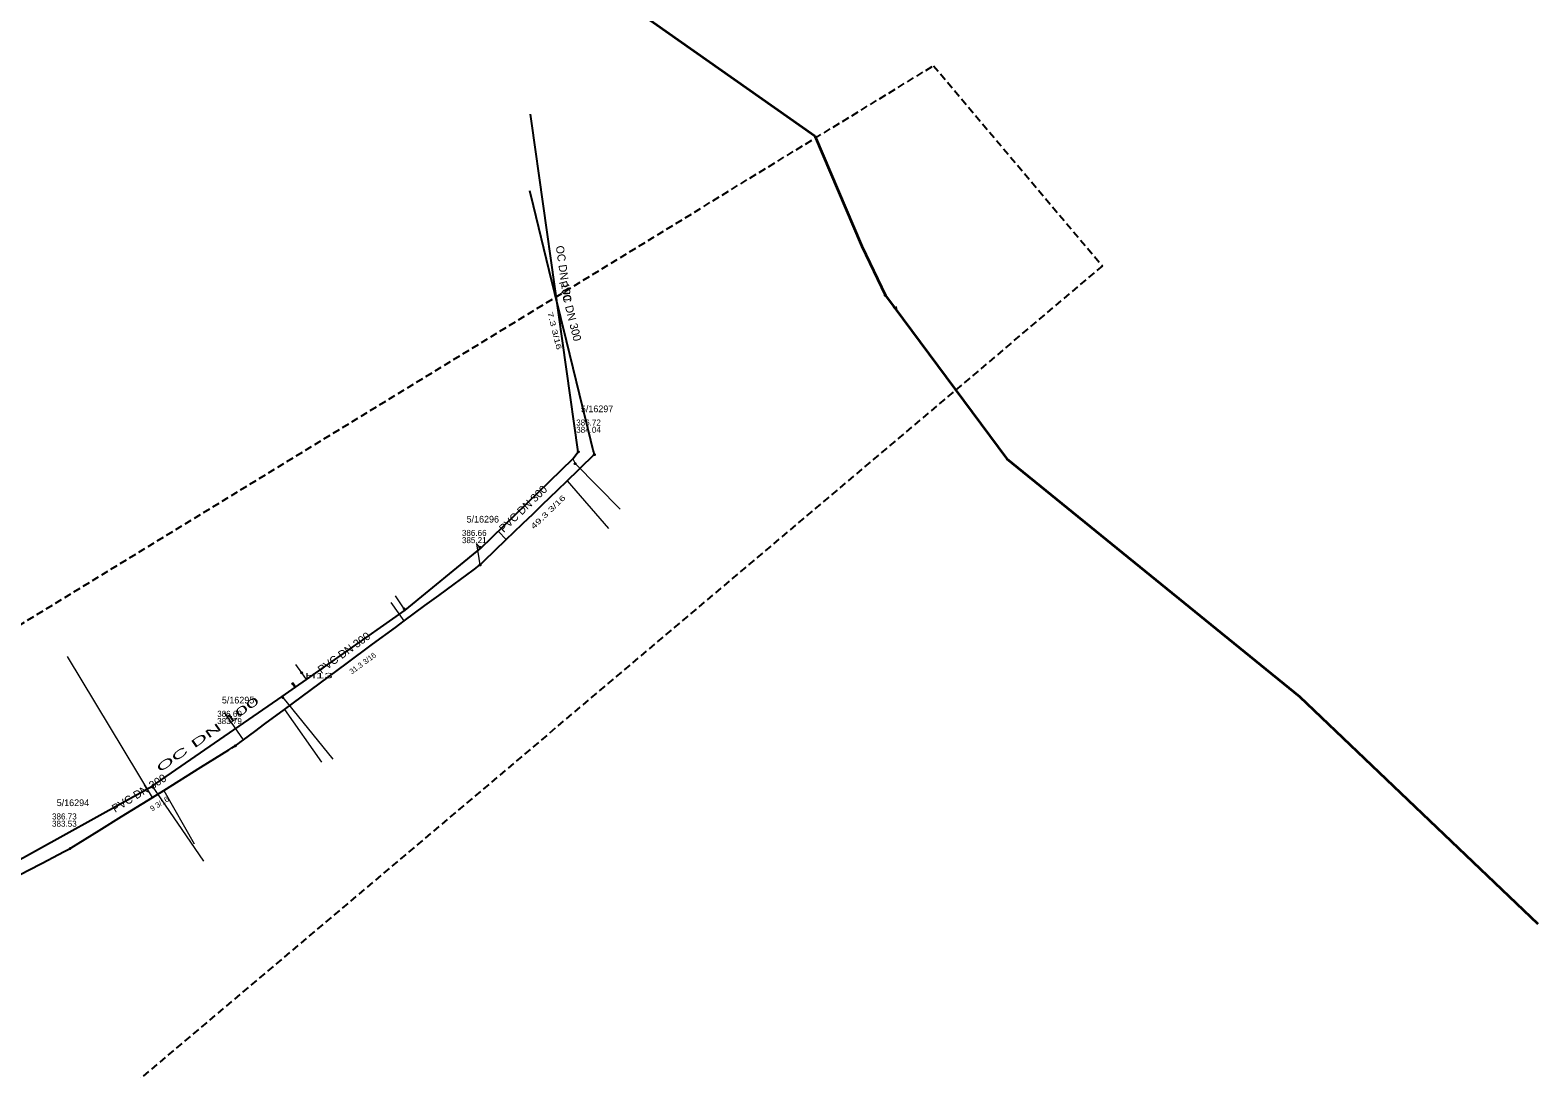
# Model space of a CAD drawing. Extents: x -772855 to -772151, y -1033136 to -1032581.
# Drawn here: x -772376 to -772151.1, y -1032956.5 to -1032801.5 of the extents above; entities that cross this region are included whole.
import ezdxf

# ---------------------------------------------------------------- set-up
doc = ezdxf.new("R2010")
doc.units = 0
doc.header["$LTSCALE"] = 0.36
doc.header["$PDMODE"] = 32
doc.header["$PDSIZE"] = 0.18
doc.linetypes.add('DOT_DASHED', pattern=[7.7, 5, -1.2, 0.3, -1.2])
doc.linetypes.add('MEDIUM_DASHED', pattern=[4.5, 3, -1.5])
for name, color, linetype in [('15', 7, 'Continuous'), ('17', 7, 'Continuous'), ('20', 7, 'Continuous'), ('21', 7, 'Continuous'), ('3', 7, 'Continuous'), ('4', 7, 'Continuous'), ('5', 7, 'Continuous'), ('56', 7, 'Continuous')]:
    doc.layers.add(name, color=color, linetype=linetype)
for name, color, linetype, lineweight in [('16', 7, 'Continuous', 25), ('2', 7, 'Continuous', 25), ('41', 7, 'DOT_DASHED', 35), ('57', 7, 'Continuous', 13), ('58', 7, 'Continuous', 13), ('62', 7, 'MEDIUM_DASHED', 25)]:
    doc.layers.add(name, color=color, linetype=linetype, lineweight=lineweight)

msp = doc.modelspace()

# ---------------------------------------------------------------- linework, layer by layer
at = {"layer": '15'}
for p in [(-772248.45, -1032841.09), (-772294.264, -1032864.446), (-772294.737, -1032866.211), (-772308.938, -1032878.708), (-772320.242, -1032887.886), (-772335.526, -1032897.422), (-772336.666, -1032899.313), (-772338.356, -1032901.119), (-772357.823, -1032914.385)]:
    msp.add_point(p, dxfattribs=at)
at = {"layer": '16', "lineweight": 35}
for points in [[(-772573.62, -1032580.91), (-772544.449, -1032601.839), (-772487.239, -1032639.739), (-772409.829, -1032692.94), (-772349.25, -1032742.28), (-772336.339, -1032755.28), (-772324.109, -1032770.089), (-772310.5, -1032781.71), (-772304.089, -1032786.42), (-772295.059, -1032791.859), (-772258.989, -1032817.269), (-772251.94, -1032833.739), (-772248.449, -1032841.089)], [(-772248.449, -1032841.089), (-772230.335, -1032865.497), (-772186.679, -1032900.96), (-772151.109, -1032934.89)]]:
    msp.add_lwpolyline(points, dxfattribs=at)
at = {"layer": '16'}
for points in [[(-772294.263, -1032864.445), (-772301.245, -1032815.115), (-772301.398, -1032814.033)], [(-772415.739, -1032946.164), (-772401.855, -1032938.587), (-772379.355, -1032926.307), (-772357.856, -1032914.338), (-772338.431, -1032900.962), (-772336.468, -1032899.579), (-772334.822, -1032898.421), (-772320.116, -1032888.065), (-772308.796, -1032878.817), (-772295.074, -1032865.513), (-772294.263, -1032864.445)]]:
    msp.add_lwpolyline(points, dxfattribs=at)
at = {"layer": '2'}
for points in [[(-772291.88, -1032864.86), (-772291.919, -1032864.697), (-772291.968, -1032864.499), (-772292.033, -1032864.215), (-772292.094, -1032863.982), (-772292.693, -1032861.525), (-772293.08, -1032859.943), (-772296.027, -1032847.87), (-772298.591, -1032837.362), (-772300.943, -1032827.729), (-772301.491, -1032825.485)], [(-772308.93, -1032881.33), (-772308.334, -1032880.754), (-772305.002, -1032877.526), (-772303.867, -1032876.439), (-772302.531, -1032875.149), (-772301.011, -1032873.68), (-772299.649, -1032872.364), (-772298.462, -1032871.218), (-772297.349, -1032870.143), (-772295.918, -1032868.76), (-772294.255, -1032867.154), (-772293.424, -1032866.352), (-772292.446, -1032865.406), (-772292.144, -1032865.115), (-772291.88, -1032864.86)], [(-772345.44, -1032908.33), (-772345.022, -1032908.021), (-772344.761, -1032907.828), (-772344.192, -1032907.408), (-772342.511, -1032906.164), (-772341.024, -1032905.064), (-772338.084, -1032902.89), (-772328.873, -1032896.078), (-772324.947, -1032893.174), (-772321.521, -1032890.641), (-772320.226, -1032889.683), (-772317.141, -1032887.402), (-772315.067, -1032885.868), (-772312.803, -1032884.194), (-772309.962, -1032882.093), (-772309.553, -1032881.791), (-772309.188, -1032881.521), (-772308.93, -1032881.33)], [(-772370.08, -1032923.65), (-772369.521, -1032923.302), (-772368.87, -1032922.897), (-772365.746, -1032920.955), (-772362.396, -1032918.872), (-772357.815, -1032916.024), (-772356.123, -1032914.972), (-772350.573, -1032911.521), (-772346.379, -1032908.913), (-772345.944, -1032908.643), (-772345.44, -1032908.33)], [(-772413.9, -1032946.45), (-772413.42, -1032946.2), (-772412.857, -1032945.907), (-772407.577, -1032943.16), (-772403.768, -1032941.178), (-772399.916, -1032939.173), (-772395.222, -1032936.731), (-772390.907, -1032934.486), (-772385.235, -1032931.535), (-772382.615, -1032930.172), (-772376.302, -1032926.887), (-772374.27, -1032925.83), (-772371.818, -1032924.554), (-772370.95, -1032924.102), (-772370.586, -1032923.913), (-772370.08, -1032923.65)]]:
    msp.add_lwpolyline(points, dxfattribs=at)
at = {"layer": '20'}
msp.add_point((-772336.863, -1032899.044), dxfattribs=at)
at = {"layer": '21'}
msp.add_point((-772248.449, -1032841.089), dxfattribs=at)
at = {"layer": '4'}
for p in [(-772291.88, -1032864.86), (-772308.93, -1032881.33), (-772345.44, -1032908.329), (-772370.08, -1032923.65)]:
    msp.add_point(p, dxfattribs=at)
at = {"layer": '41', "linetype": 'Continuous', "lineweight": 13}
for q in [(-772247.209, -1032842.807), (-772247.209, -1032842.807), (-772247.209, -1032842.807), (-772247.209, -1032842.807), (-772246.749, -1032843.195), (-772246.749, -1032843.195), (-772246.749, -1032843.195), (-772246.749, -1032843.195)]:
    msp.add_line((-772246.974, -1032842.99), q, dxfattribs=at)
at = {"layer": '41'}
for q in [(-772247.209, -1032842.807), (-772247.209, -1032842.807), (-772247.209, -1032842.807), (-772247.209, -1032842.807), (-772247.209, -1032842.807), (-772247.209, -1032842.807), (-772247.209, -1032842.807), (-772247.209, -1032842.807), (-772246.749, -1032843.195), (-772246.749, -1032843.195), (-772246.749, -1032843.195), (-772246.749, -1032843.195), (-772246.749, -1032843.195), (-772246.749, -1032843.195), (-772246.749, -1032843.195), (-772246.749, -1032843.195)]:
    msp.add_line((-772246.974, -1032842.99), q, dxfattribs=at)
at = {"layer": '41', "linetype": 'MEDIUM_DASHED', "lineweight": 25}
msp.add_line((-772246.974, -1032842.99), (-772246.731, -1032842.736), dxfattribs=at)
msp.add_line((-772246.974, -1032842.99), (-772246.731, -1032842.736), dxfattribs=at)
msp.add_line((-772246.974, -1032842.99), (-772246.731, -1032842.736), dxfattribs=at)
msp.add_line((-772246.974, -1032842.99), (-772246.731, -1032842.736), dxfattribs=at)
at = {"layer": '56'}
msp.add_point((-772246.974, -1032842.99), dxfattribs=at)
at = {"layer": '57'}
for p, q in [((-772295.918, -1032868.76), (-772289.77, -1032875.91)), ((-772305.002, -1032877.526), (-772306.15, -1032876.33)), ((-772308.93, -1032881.33), (-772309.381, -1032878.18)), ((-772320.226, -1032889.683), (-772322.18, -1032886.95)), ((-772357.815, -1032916.024), (-772370.48, -1032894.99)), ((-772338.084, -1032902.89), (-772332.59, -1032910.75)), ((-772356.123, -1032914.972), (-772351.59, -1032922.94))]:
    msp.add_line(p, q, dxfattribs=at)
msp.add_lwpolyline([(-772344.192, -1032907.408), (-772346.001, -1032904.823), (-772347.04, -1032903.34)], dxfattribs=at)
at = {"layer": '58'}
for p, q in [((-772338.431, -1032900.962), (-772338.356, -1032901.119)), ((-772338.355, -1032901.118), (-772330.887, -1032910.328)), ((-772357.856, -1032914.338), (-772350.181, -1032925.515))]:
    msp.add_line(p, q, dxfattribs=at)
for points in [[(-772295.074, -1032865.514), (-772294.738, -1032866.211), (-772287.994, -1032873.011)], [(-772308.796, -1032878.816), (-772308.938, -1032878.708), (-772309.463, -1032878.124)], [(-772320.117, -1032888.065), (-772320.242, -1032887.886), (-772321.513, -1032885.928)], [(-772334.823, -1032898.421), (-772335.526, -1032897.422), (-772336.395, -1032896.189)], [(-772336.468, -1032899.579), (-772336.666, -1032899.313), (-772336.863, -1032899.044)]]:
    msp.add_lwpolyline(points, dxfattribs=at)
at = {"layer": '62'}
msp.add_lwpolyline([(-772807.858, -1033073.22), (-772807.858, -1033073.204), (-772761.644, -1033042.737), (-772462.077, -1032942.017), (-772241.248, -1032806.814), (-772216.072, -1032836.7), (-772367.717, -1032964.854), (-772756.015, -1033111.568)], close=True, dxfattribs=at)

# ---------------------------------------------------------------- texts
at = {"layer": '17'}
msp.add_text('OC DN 100 ', height=1.2, rotation=278, dxfattribs=at).set_placement((-772297.625, -1032833.756))
at = {"layer": '17', "width": 2.2}
msp.add_text('OC DN 100 ', height=1.2, rotation=35, dxfattribs=at).set_placement((-772356.687, -1032912.339))
at = {"layer": '20', "width": 2.1}
msp.add_text('H13 ', height=0.8, dxfattribs=at).set_placement((-772335.037, -1032898.239))
at = {"layer": '3'}
for s, height, rotation, p in [('PVC DN 300', 1.2, 284, (-772297.164, -1032839.111)), ('PVC DN 300', 1.2, 44, (-772305.395, -1032876.564)), ('PVC DN 300', 1.2, 36, (-772332.587, -1032897.615)), ('31.3 3/16', 0.8, 36, (-772328.058, -1032897.683)), ('PVC DN 300', 1.2, 32, (-772363.368, -1032918.332)), ('9 3/16 ', 0.8, 32, (-772357.84, -1032918.131))]:
    msp.add_text(s, height=height, rotation=rotation, dxfattribs=at).set_placement(p)
at = {"layer": '3', "width": 1.5}
for s, rotation, p in [('7.3 3/16 ', 284, (-772298.884, -1032843.65)), ('49.3 3/16', 44, (-772300.895, -1032876.039))]:
    msp.add_text(s, height=0.8, rotation=rotation, dxfattribs=at).set_placement(p)
at = {"layer": '5'}
for s, p in [('5/16297', (-772293.88, -1032858.531)), ('5/16296', (-772310.93, -1032875.001)), ('5/16295', (-772347.44, -1032902.001)), ('5/16294', (-772372.08, -1032917.321))]:
    msp.add_text(s, height=1, dxfattribs=at).set_placement(p)
at = {"layer": '56'}
for s, p in [('386.72', (-772294.578, -1032860.527)), ('384.04', (-772294.578, -1032861.604)), ('386.66', (-772311.628, -1032876.997)), ('385.21', (-772311.628, -1032878.074)), ('386.60', (-772348.138, -1032903.998)), ('383.79', (-772348.138, -1032905.075)), ('386.73', (-772372.778, -1032919.317)), ('383.53', (-772372.778, -1032920.394))]:
    msp.add_text(s, height=0.9, dxfattribs=at).set_placement(p)

doc.saveas('drawing.dxf')
